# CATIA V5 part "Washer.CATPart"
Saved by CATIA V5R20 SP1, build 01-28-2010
Part number: washer
Bounding box of the stored display mesh (mm): x -24 to 24, y -23.825 to 23.825, z 0 to 3
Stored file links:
  D:\v5_r20\psrt_files_downloaded\c14\c14-catia-v5r20-figr-14-26 & 27\Part & Asm\Washer.CATPart
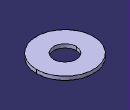
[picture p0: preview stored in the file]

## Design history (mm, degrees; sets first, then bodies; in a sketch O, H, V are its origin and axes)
Body1 (main body)
  Sketch1 on xy-plane, origin (0, 0, 0), H (1, 0, 0), V (0, 1, 0)
    circle A1 centre (0, 0) radius 24
    circle A2 centre (0, 0) radius 9.5
    radius A1 = 24
    radius A2 = 9.5
  Pad1: profile Sketch1, direction (0, 0, 1), length 3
